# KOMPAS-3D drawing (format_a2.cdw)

Views: Вид 1, Вид 2, Вид 3, Выносной элемент А, Выносной элемент, Выносной элемент Б
Referenced files in D:\Program Files\ASCON\KOMPAS-3D LT V11\Sys\: Graphic.lcs
Referenced files: Металлоконструкция.cdw
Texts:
  КП.1.О.4054.
  Карта  металлоконструкции
  User
  Noncommercial version
  Текст на чертеже
  Размерные надписи
  Шероховатость
  Линия-выноска #1
  Линия-выноска #2
  Линия-выноска #3
  Отклонения формы и база
  Заголовок таблицы
  Ячейка таблицы
  Стрелка вида
  Обозначение изменения
  Фигурная скобка
  Номер узла
  Марка координационной оси
  VRCB
  Выносная надпись
  Обозначение узла
  Марка/позиционное обозначение с линией-выноской
  Марка/позиционное обозначение на линии
  Марка/позиционное обозначение без линии-выноски
  Эпюра Q, кН
  Эпюра М, кНм
  ГОСТ5264-80-С8
  Скрытая линия
  Сварные швы
  ГОСТ 15-1932
  ГОСТ 8510-86*
  Карта
  металлоконструкции
  Дружинин
  Реутов
  Фомич
  Капустин
Dimensions and other numbers on the sheet: 7; 0,987; 0,411; 50; 100; 80; 20; 10; 2500; 1700; 1000; 40; 63; 4; 1; 2; 3; 1 - Опорная стойка; 2 - Подхватывающая балка; 3 - Балка; 4 - ГОСТ5264-80-Н1; 213; 1400; 445; 60; 90; 620; 276; 248; 415; 0,7583; 0,746; 0,6343; 1:14,3; 0; 5; 6; 8; 9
